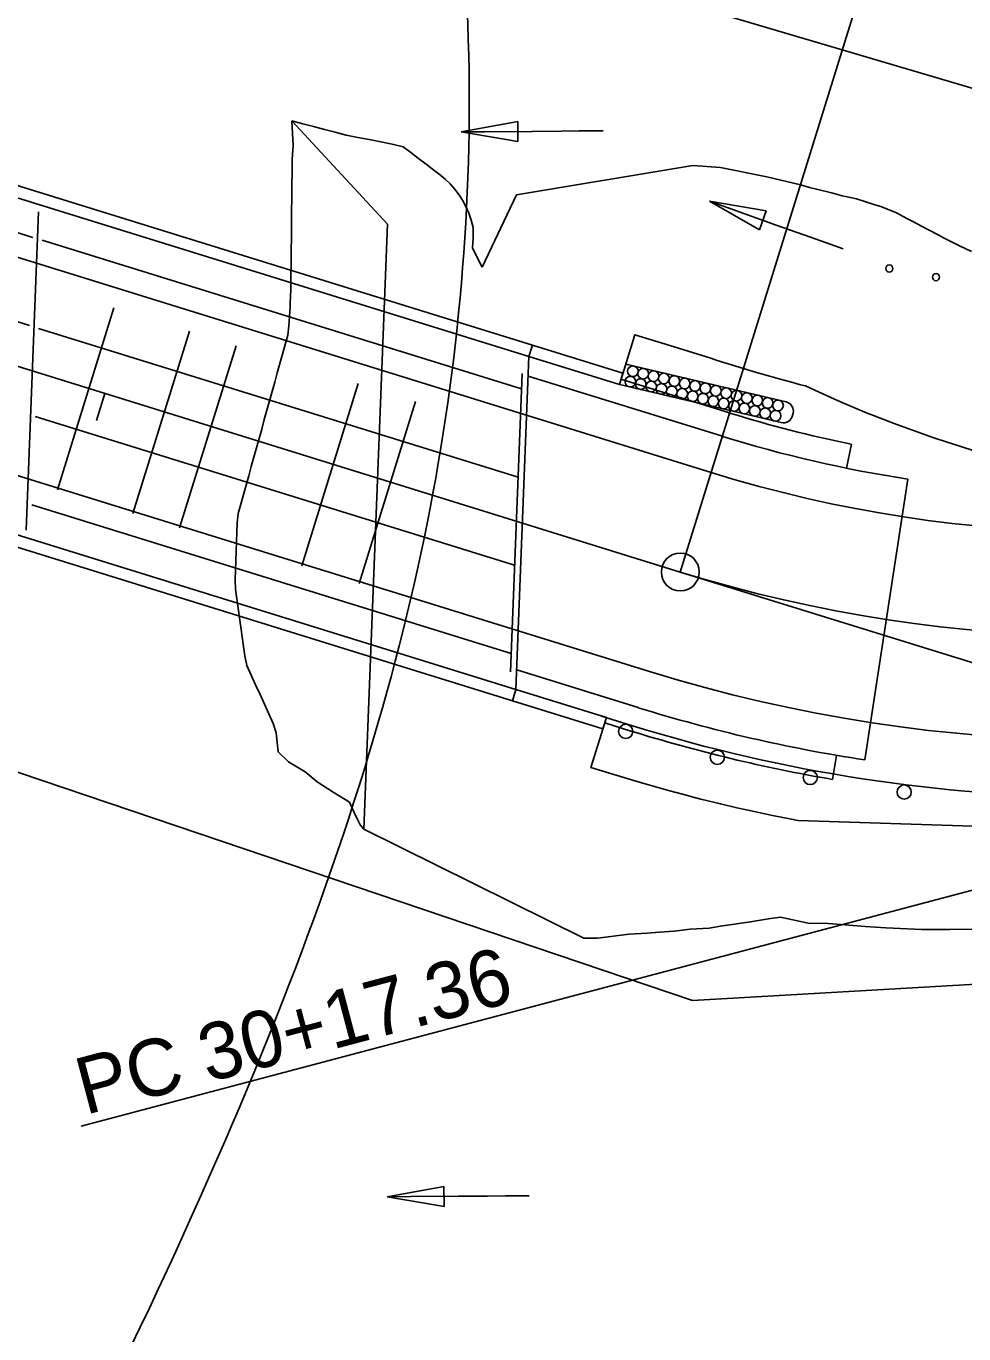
# Model space of a CAD drawing. Extents: x 1 to 1477871, y 1 to 1872901.
# Drawn here: x 1443824.9 to 1443923.9, y 1854893.5 to 1855031.6 of the extents above; entities that cross this region are included whole.
import ezdxf

# ---------------------------------------------------------------- set-up
doc = ezdxf.new("R2010")
doc.units = 0
for name, color, linetype in [('B_Centerline', 7, 'Continuous'), ('B_Concrete', 7, 'Continuous'), ('R_Floodplain', 7, 'Continuous'), ('R_Horz Alg', 7, 'Continuous'), ('R_Horz Alg Annot', 7, 'Continuous'), ('R_No Plot', 7, 'Continuous'), ('R_Proposed Const Limits_Cut', 7, 'Continuous'), ('R_Proposed Const Limits_Fill', 7, 'Continuous'), ('R_Proposed Const Limits_Hand', 7, 'Continuous'), ('R_Proposed Road_Lane', 7, 'Continuous'), ('R_Proposed Road_Shoulder', 7, 'Continuous'), ('R_ROW', 7, 'Continuous'), ('R_Steel', 7, 'Continuous'), ('R_Water', 7, 'Continuous')]:
    doc.layers.add(name, color=color, linetype=linetype)

msp = doc.modelspace()

# ---------------------------------------------------------------- linework, layer by layer
at = {"layer": 'B_Centerline'}
msp.add_line((1443826.22, 1855011.96), (1443824.91, 1854978.34), dxfattribs=at)
at = {"layer": 'B_Concrete'}
for p, q in [((1443722.94, 1855044.78), (1443877.99, 1854996.69)), ((1443723.31, 1855045.98), (1443878.36, 1854997.88)), ((1443876.62, 1854961.52), (1443721.57, 1855009.61)), ((1443876.25, 1854960.32), (1443721.2, 1855008.42)), ((1443878.36, 1854997.88), (1443877.99, 1854996.69)), ((1443887.91, 1854994.92), (1443878.36, 1854997.88)), ((1443877.99, 1854996.69), (1443876.62, 1854961.52)), ((1443887.54, 1854993.73), (1443877.99, 1854996.69)), ((1443877.91, 1854994.62), (1443898.42, 1854988.26)), ((1443887.91, 1854994.92), (1443887.54, 1854993.73)), ((1443887.71, 1854994.29), (1443899.18, 1854990.73)), ((1443912.03, 1854987.43), (1443911.51, 1854984.9)), ((1443918, 1854983.74), (1443913.44, 1854954.09)), ((1443889.53, 1854959.61), (1443876.7, 1854963.59)), ((1443876.25, 1854960.32), (1443876.62, 1854961.52)), ((1443886.17, 1854958.56), (1443876.62, 1854961.52)), ((1443885.8, 1854957.36), (1443876.25, 1854960.32)), ((1443885.8, 1854957.36), (1443886.17, 1854958.56)), ((1443888.76, 1854957.14), (1443885.99, 1854958)), ((1443910.04, 1854952.03), (1443910.48, 1854954.57))]:
    msp.add_line(p, q, dxfattribs=at)
for radius, end in [(133.2, 258.4752), (135.78, 261.2571), (165.78, 261.2571), (168.36, 260.2202)]:
    msp.add_arc((1443938.64, 1855117.94), radius, 252.7667, end, dxfattribs=at)
at = {"layer": 'R_Floodplain'}
msp.add_open_spline([(1444534.23, 1857777.84), (1444398.78, 1857609.12), (1444367.89, 1857131.47), (1444306.1, 1856808.28), (1444134.95, 1856378.26), (1444024.62, 1856227.92), (1443837.91, 1855964.82), (1443664.53, 1855852.06), (1443479.03, 1855867.82), (1443335.96, 1855886.01), (1443298.37, 1855854.49), (1443356.57, 1855756.28), (1443606.51, 1855482.27), (1443757.19, 1855307.33), (1443863.11, 1855113.58), (1443878.59, 1855007.91), (1443849.87, 1854910.07), (1443760.66, 1854753.08), (1443429.28, 1854512.04), (1443240.87, 1854371.16), (1443115.26, 1854254.04), (1443060.94, 1853889.1), (1443099.99, 1853680.31), (1443032.09, 1853386.66), (1443001.54, 1853198.25), (1444534.23, 1857777.84), (1443001.54, 1853198.25)], degree=3, dxfattribs=at)
at = {"layer": 'R_Horz Alg'}
msp.add_line((1443635.98, 1855053.96), (1443893.97, 1854973.93), dxfattribs=at)
msp.add_line((1443635.98, 1855053.96), (1443893.97, 1854973.93), dxfattribs=at)
msp.add_arc((1443938.64, 1855117.94), 150.78, 252.7667, 320, dxfattribs=at)
msp.add_arc((1443938.64, 1855117.94), 150.78, 252.7667, 320, dxfattribs=at)
at = {"layer": 'R_Horz Alg Annot'}
msp.add_line((1443893.97, 1854973.93), (1443989.71, 1854944.24), dxfattribs=at)
for points in [[(1443893.97, 1854973.93), (1443929.52, 1855088.55)], [(1443832.32, 1854989.92), (1443833.21, 1854992.78)], [(1443981.68, 1854955.41), (1443830.71, 1854915.43)]]:
    msp.add_lwpolyline(points, dxfattribs=at)
msp.add_circle((1443893.97, 1854973.93), 2, dxfattribs=at)
at = {"layer": 'R_No Plot'}
for p, q in [((1443775.01, 1855024.97), (1443825.63, 1855009.27)), ((1443774.65, 1855015.66), (1443825.27, 1854999.96)), ((1443826.59, 1855008.97), (1443877.21, 1854993.27)), ((1443828.22, 1854982.6), (1443834.18, 1855001.83)), ((1443826.23, 1854999.66), (1443876.85, 1854983.96)), ((1443842.15, 1854999.35), (1443836.19, 1854980.12)), ((1443841.11, 1854978.6), (1443847.07, 1854997.83)), ((1443854, 1854974.6), (1443859.97, 1854993.83)), ((1443877.27, 1854994.9), (1443876.04, 1854963.38)), ((1443866.03, 1854991.95), (1443860.06, 1854972.72)), ((1443825.86, 1854990.35), (1443876.48, 1854974.65)), ((1443825.5, 1854981.04), (1443876.12, 1854965.34))]:
    msp.add_line(p, q, dxfattribs=at)
at = {"layer": 'R_Proposed Const Limits_Cut'}
msp.add_lwpolyline([(1443895.28, 1855016.85), (1443898.2, 1855016.65), (1443903.12, 1855015.65), (1443906.65, 1855014.82), (1443907.61, 1855014.55), (1443908.35, 1855014.35), (1443910.06, 1855013.92), (1443911.07, 1855013.67), (1443911.77, 1855013.51), (1443912.57, 1855013.33), (1443913.46, 1855013.04), (1443914.52, 1855012.71), (1443915.15, 1855012.53), (1443916.81, 1855011.87), (1443917.89, 1855011.27), (1443918.44, 1855010.97), (1443920.09, 1855010.09), (1443921.25, 1855009.49), (1443921.76, 1855009.23), (1443923.45, 1855008.39), (1443924.71, 1855007.78)], dxfattribs=at)
at = {"layer": 'R_Proposed Const Limits_Fill'}
for points in [[(1443873.06, 1855006.13), (1443876.68, 1855013.76), (1443895.28, 1855016.85)], [(1443860.57, 1854946.79), (1443883.8, 1854935.25), (1443885.23, 1854935.27), (1443888.56, 1854935.7), (1443890.49, 1854935.81), (1443891.79, 1854935.9), (1443893.31, 1854936.01), (1443895.02, 1854936.2), (1443897.01, 1854936.31), (1443898.21, 1854936.55), (1443901.4, 1854936.98), (1443903.51, 1854937.34), (1443904.55, 1854937.48), (1443907.48, 1854936.84), (1443909.6, 1854936.8), (1443910.49, 1854936.73), (1443913.48, 1854936.49), (1443915.67, 1854936.35), (1443916.46, 1854936.31), (1443919.45, 1854936.18), (1443921.75, 1854936.17), (1443922.44, 1854936.17), (1443925.42, 1854936.22)]]:
    msp.add_lwpolyline(points, dxfattribs=at)
at = {"layer": 'R_Proposed Const Limits_Hand'}
for points in [[(1443852.96, 1855021.57), (1443853.03, 1855020.27), (1443853.1, 1855018.97), (1443853, 1855017.52), (1443852.99, 1855016.14), (1443852.97, 1855014.77), (1443852.96, 1855013.39), (1443852.94, 1855012.02), (1443852.93, 1855010.64), (1443852.92, 1855009.27), (1443852.9, 1855007.89), (1443852.89, 1855006.52), (1443852.87, 1855005.14), (1443852.86, 1855003.77), (1443852.79, 1855002.34), (1443852.77, 1855001.92), (1443852.7, 1855000.92), (1443852.64, 1854999.92), (1443852.52, 1854998.93), (1443852.25, 1854997.94), (1443851.97, 1854996.95), (1443851.7, 1854995.96), (1443851.42, 1854994.97), (1443851.15, 1854993.98), (1443850.88, 1854992.99), (1443850.6, 1854992), (1443850.33, 1854991.01), (1443850.05, 1854990.02), (1443849.78, 1854989.03), (1443849.5, 1854988.04), (1443849.23, 1854987.05), (1443848.95, 1854986.06), (1443848.68, 1854985.07), (1443848.41, 1854984.08), (1443848.13, 1854983.09), (1443847.86, 1854982.1), (1443847.58, 1854981.11), (1443847.31, 1854980.12), (1443847.19, 1854979.12), (1443847.16, 1854978.12), (1443847.12, 1854977.12), (1443847.09, 1854976.12), (1443847.05, 1854975.12), (1443847.01, 1854974.12), (1443846.98, 1854973.12), (1443847.01, 1854972.12), (1443847.15, 1854971.11), (1443847.29, 1854970.11), (1443847.43, 1854969.1), (1443847.57, 1854968.1), (1443847.71, 1854967.09), (1443847.86, 1854966.08), (1443848, 1854965.08), (1443848.22, 1854964.07), (1443848.68, 1854963.05), (1443849.14, 1854962.03), (1443849.6, 1854961.01), (1443850.06, 1854959.99), (1443850.52, 1854958.97), (1443850.98, 1854957.95), (1443851.3, 1854956.94), (1443851.42, 1854955.94), (1443851.53, 1854954.93), (1443852.59, 1854953.89), (1443854.35, 1854952.82), (1443855.63, 1854951.77), (1443857.34, 1854950.7), (1443859.03, 1854949.64), (1443859.51, 1854948.62), (1443860, 1854947.6), (1443860.17, 1854947.24), (1443860.57, 1854946.79)], [(1443852.96, 1855021.57), (1443854.11, 1855021.27), (1443855.25, 1855020.97), (1443856.4, 1855020.67), (1443857.55, 1855020.37), (1443858.71, 1855020.07), (1443859.92, 1855019.83), (1443861.13, 1855019.59), (1443862.35, 1855019.35), (1443863.55, 1855019.1), (1443864.73, 1855018.83), (1443865.54, 1855018.22), (1443866.34, 1855017.6), (1443867.15, 1855016.98), (1443867.95, 1855016.37), (1443868.66, 1855015.83), (1443869.18, 1855015.39), (1443869.68, 1855014.91), (1443870.15, 1855014.38), (1443870.59, 1855013.81), (1443870.99, 1855013.19), (1443871.34, 1855012.53), (1443871.65, 1855011.82), (1443871.9, 1855011.08), (1443872.1, 1855010.3), (1443872.12, 1855010.17), (1443872.1, 1855009.17), (1443872.04, 1855008.17), (1443872.52, 1855007.15), (1443873.06, 1855006.13)], [(1443852.96, 1855021.57), (1443863.06, 1855010.65), (1443860.57, 1854946.79)]]:
    msp.add_lwpolyline(points, dxfattribs=at)
at = {"layer": 'R_Proposed Road_Lane'}
for p, q in [((1443639.24, 1855064.47), (1443897.23, 1854984.44)), ((1443632.72, 1855043.45), (1443890.71, 1854963.43))]:
    msp.add_line(p, q, dxfattribs=at)
for radius in [139.78, 161.78]:
    msp.add_arc((1443938.64, 1855117.94), radius, 252.7667, 320, dxfattribs=at)
at = {"layer": 'R_Proposed Road_Shoulder'}
msp.add_line((1443906.42, 1854947.69), (1443939.55, 1854946.62), dxfattribs=at)
for points in [[(1443887.54, 1854993.73), (1443889.17, 1854998.98), (1443892.41, 1854997.98), (1443897.18, 1854996.5), (1443897.87, 1854996.28), (1443900.64, 1854995.42), (1443901.76, 1854995.08), (1443902.64, 1854994.82), (1443904.65, 1854994.25), (1443905.85, 1854993.93), (1443906.67, 1854993.71), (1443907.18, 1854993.58), (1443908.63, 1854992.91), (1443909.86, 1854992.36), (1443910.58, 1854992.04), (1443912.55, 1854991.2), (1443913.88, 1854990.65), (1443914.46, 1854990.42), (1443914.55, 1854990.39), (1443916.56, 1854989.61), (1443917.98, 1854989.08), (1443918.59, 1854988.86), (1443920.64, 1854988.14), (1443922.16, 1854987.64), (1443922.71, 1854987.46), (1443924.8, 1854986.81)], [(1443886.17, 1854958.56), (1443884.54, 1854953.3), (1443887.31, 1854952.44), (1443888.82, 1854951.98), (1443890.01, 1854951.63), (1443892.73, 1854950.86), (1443894.35, 1854950.42), (1443895.46, 1854950.13), (1443896.14, 1854949.96), (1443898.2, 1854949.45), (1443899.93, 1854949.04), (1443900.95, 1854948.81), (1443903.71, 1854948.22), (1443905.55, 1854947.85), (1443906.37, 1854947.7), (1443906.42, 1854947.69)]]:
    msp.add_lwpolyline(points, dxfattribs=at)
at = {"layer": 'R_ROW'}
for p, q in [((1443565.8, 1855131.35), (1443949.34, 1855017.73)), ((1443436.56, 1855083.7), (1443895.27, 1854928.7)), ((1443895.27, 1854928.7), (1444023.78, 1854936.11))]:
    msp.add_line(p, q, dxfattribs=at)
at = {"layer": 'R_Steel'}
for p, q in [((1443887.54, 1854993.73), (1443888.21, 1854995.88)), ((1443888.21, 1854995.88), (1443905.14, 1854991.9)), ((1443887.54, 1854993.73), (1443904.62, 1854989.71)), ((1443905.88, 1854990.7), (1443905.83, 1854990.45)), ((1443885.66, 1854958.71), (1443888.94, 1854957.7))]:
    msp.add_line(p, q, dxfattribs=at)
for centre, radius in [((1443888.96, 1854995.13), 0.563), ((1443888.96, 1854995.13), 0.563), ((1443890.05, 1854994.87), 0.563), ((1443891.15, 1854994.61), 0.563), ((1443888.7, 1854994.03), 0.563), ((1443888.7, 1854994.03), 0.563), ((1443889.79, 1854993.78), 0.563), ((1443890.89, 1854993.52), 0.563), ((1443891.98, 1854993.26), 0.563), ((1443892.24, 1854994.36), 0.563), ((1443893.34, 1854994.1), 0.563), ((1443894.43, 1854993.84), 0.563), ((1443895.53, 1854993.58), 0.563), ((1443896.62, 1854993.33), 0.563), ((1443893.08, 1854993), 0.563), ((1443894.17, 1854992.75), 0.563), ((1443895.27, 1854992.49), 0.563), ((1443896.36, 1854992.23), 0.563), ((1443897.46, 1854991.97), 0.563), ((1443897.72, 1854993.07), 0.563), ((1443898.55, 1854991.72), 0.563), ((1443898.81, 1854992.81), 0.563), ((1443899.91, 1854992.55), 0.563), ((1443901, 1854992.29), 0.563), ((1443902.1, 1854992.04), 0.563), ((1443903.19, 1854991.78), 0.563), ((1443899.65, 1854991.46), 0.563), ((1443900.74, 1854991.2), 0.563), ((1443901.84, 1854990.94), 0.563), ((1443902.93, 1854990.69), 0.563), ((1443904.03, 1854990.43), 0.563), ((1443904.29, 1854991.52), 0.563), ((1443888.21, 1854957.1), 0.75), ((1443897.88, 1854954.37), 0.75), ((1443907.69, 1854952.23), 0.75), ((1443917.61, 1854950.69), 0.75)]:
    msp.add_circle(centre, radius, dxfattribs=at)
for centre, radius, start, end in [((1443904.91, 1854990.93), 1, 346.7648, 76.7648), ((1443904.85, 1854990.68), 1, 256.7648, 346.7648), ((1443938.64, 1855117.94), 167.78, 252.7667, 269.7843)]:
    msp.add_arc(centre, radius, start, end, dxfattribs=at)
at = {"layer": 'R_Water'}
for p, q in [((1443876.82, 1855021.51), (1443870.83, 1855020.4)), ((1443876.83, 1855019.39), (1443876.82, 1855021.51)), ((1443870.83, 1855020.4), (1443876.83, 1855019.39)), ((1443897.05, 1855013.08), (1443902.35, 1855010.08)), ((1443903.05, 1855012.07), (1443897.05, 1855013.08)), ((1443902.35, 1855010.08), (1443903.05, 1855012.07)), ((1443869.01, 1854909.05), (1443863.02, 1854907.95)), ((1443869.03, 1854906.94), (1443869.01, 1854909.05)), ((1443863.02, 1854907.95), (1443869.03, 1854906.94))]:
    msp.add_line(p, q, dxfattribs=at)
for points in [[(1443885.83, 1855020.52), (1443883.31, 1855020.5), (1443881.42, 1855020.48), (1443878.32, 1855020.46), (1443873.34, 1855020.42), (1443870.83, 1855020.4)], [(1443911.18, 1855008.07), (1443908.81, 1855008.91), (1443907.03, 1855009.54), (1443904.11, 1855010.57), (1443899.41, 1855012.24), (1443897.05, 1855013.08)], [(1443878.02, 1854908.06), (1443875.5, 1854908.04), (1443873.62, 1854908.03), (1443870.52, 1854908.01), (1443865.53, 1854907.97), (1443863.02, 1854907.95)]]:
    msp.add_lwpolyline(points, dxfattribs=at)
for centre in [(1443916.04, 1855005.98), (1443920.97, 1855005.07)]:
    msp.add_circle(centre, 0.375, dxfattribs=at)

# ---------------------------------------------------------------- texts
at = {"layer": 'R_Horz Alg Annot'}
msp.add_text('PC 30+17.36', height=6, rotation=14.8311, dxfattribs=at).set_placement((1443831.14, 1854916.58))

doc.saveas('drawing.dxf')
